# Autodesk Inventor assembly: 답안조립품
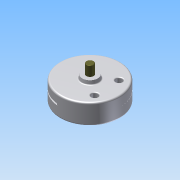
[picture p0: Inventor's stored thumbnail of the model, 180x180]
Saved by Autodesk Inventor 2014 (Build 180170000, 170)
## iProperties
Created: 2015-06
Part Number: 답안조립품
Document SubType Name: Assembly
Designer: Administrator
Author: Administrator
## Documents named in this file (5)
- C:\Documents and Settings\Administrator\바탕 화면\450631V1021\답안조립품.iam
- C:\Documents and Settings\Administrator\바탕 화면\450631V1021\덮개.ipt
- C:\Documents and Settings\Administrator\바탕 화면\450631V1021\베어링62_22.ipt
- C:\Documents and Settings\Administrator\바탕 화면\450631V1021\멈춤링.ipt
- C:\Documents and Settings\Administrator\바탕 화면\450631V1021\축.ipt
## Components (4 placed, 2 different names)
1. KS B 2023 62/22 - 22 x 50 x 14:1
2. KS B 1336 22 x 1.2:1
3. KS B 1336 22 x 1.2:2
4. KS B 2023 62/22 - 22 x 50 x 14:2
